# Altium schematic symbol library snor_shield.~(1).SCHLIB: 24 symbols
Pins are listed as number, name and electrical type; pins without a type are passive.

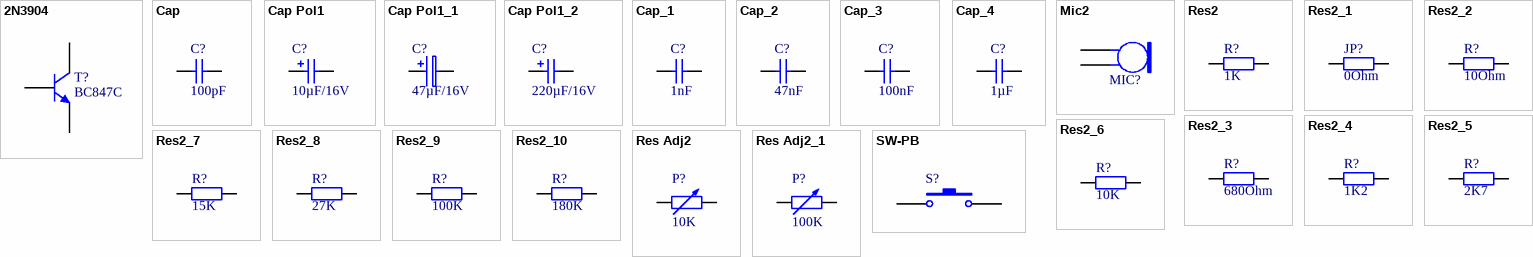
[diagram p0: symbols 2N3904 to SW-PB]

## 2N3904
designator T?, comment BC847C
NPN General Purpose Amplifier
footprint TO-92A (TO, Flat Index; 3 In-Line, Axial Leads; Body Dia. 4.5mm; Leads 0.51 x 0.48 mm (max))
simulation model 2N3904 (NPN)
signal-integrity model 2N3904
pins: 1 E, 2 B, 3 C

## Cap
designator C?  value 100pF  (hidden comment: Cap)
Capacitor
footprint RAD-0.3 (Radial Cap, Thru-Hole; 2 Leads; 0.3 in Pin Spacing)
simulation model CAP (Capacitor)
signal-integrity model Cap
pins: 1, 2

## Cap Pol1
designator C?  value 10µF/16V  (hidden comment: Cap Pol1)
Polarized Capacitor (Radial)
footprint RB7.6-15 (Polarized Capacitor (Radial); 2 Leads)
simulation model CAP (Capacitor)
signal-integrity model Cap Pol
pins: 1, 2
1 alternate drawing of the same symbol

## Cap Pol1_1
designator C?, comment value 47µF/16V  (hidden comment: Cap Pol1)
Polarized Capacitor (Radial)
footprint RB7.6-15 (Polarized Capacitor (Radial); 2 Leads)
simulation model CAP (Capacitor)
signal-integrity model Cap Pol
pins: 1, 2
1 alternate drawing of the same symbol

## Cap Pol1_2
designator C?, comment value 220µF/16V  (hidden comment: Cap Pol1)
Polarized Capacitor (Radial)
footprint RB7.6-15 (Polarized Capacitor (Radial); 2 Leads)
simulation model CAP (Capacitor)
signal-integrity model Cap Pol
pins: 1, 2
1 alternate drawing of the same symbol

## Cap_1
designator C?, comment value 1nF  (hidden comment: Cap)
Capacitor
footprint RAD-0.3 (Radial Cap, Thru-Hole; 2 Leads; 0.3 in Pin Spacing)
simulation model CAP (Capacitor)
signal-integrity model Cap
pins: 1, 2

## Cap_2
designator C?, comment value 47nF  (hidden comment: Cap)
Capacitor
footprint RAD-0.3 (Radial Cap, Thru-Hole; 2 Leads; 0.3 in Pin Spacing)
simulation model CAP (Capacitor)
signal-integrity model Cap
pins: 1, 2

## Cap_3
designator C?, comment value 100nF  (hidden comment: Cap)
Capacitor
footprint RAD-0.3 (Radial Cap, Thru-Hole; 2 Leads; 0.3 in Pin Spacing)
simulation model CAP (Capacitor)
signal-integrity model Cap
pins: 1, 2

## Cap_4
designator C?, comment value 1µF  (hidden comment: Cap)
Capacitor
footprint RAD-0.3 (Radial Cap, Thru-Hole; 2 Leads; 0.3 in Pin Spacing)
simulation model CAP (Capacitor)
signal-integrity model Cap
pins: 1, 2

## Mic2
designator MIC?  (value not drawn)
Microphone
footprint PIN2 (Microphone; 2 Leads)
pins: 1, 2

## Res2
designator R?  value 1K  (hidden comment: Res2)
Resistor
footprint AXIAL-0.4 (Axial Device, Thru-Hole; 2 Leads; 0.4 in Pin Spacing)
simulation model RESISTOR (Resistor)
signal-integrity model Res
pins: 1, 2

## Res2_1
designator JP?, comment value 0Ohm  (hidden comment: Res2)
Resistor
footprint AXIAL-0.4 (Axial Device, Thru-Hole; 2 Leads; 0.4 in Pin Spacing)
simulation model RESISTOR (Resistor)
signal-integrity model Res
pins: 1, 2

## Res2_2
designator R?, comment value 10Ohm  (hidden comment: Res2)
Resistor
footprint AXIAL-0.4 (Axial Device, Thru-Hole; 2 Leads; 0.4 in Pin Spacing)
simulation model RESISTOR (Resistor)
signal-integrity model Res
pins: 1, 2

## Res2_3
designator R?, comment value 680Ohm  (hidden comment: Res2)
Resistor
footprint AXIAL-0.4 (Axial Device, Thru-Hole; 2 Leads; 0.4 in Pin Spacing)
simulation model RESISTOR (Resistor)
signal-integrity model Res
pins: 1, 2

## Res2_4
designator R?, comment value 1K2  (hidden comment: Res2)
Resistor
footprint AXIAL-0.4 (Axial Device, Thru-Hole; 2 Leads; 0.4 in Pin Spacing)
simulation model RESISTOR (Resistor)
signal-integrity model Res
pins: 1, 2

## Res2_5
designator R?, comment value 2K7  (hidden comment: Res2)
Resistor
footprint AXIAL-0.4 (Axial Device, Thru-Hole; 2 Leads; 0.4 in Pin Spacing)
simulation model RESISTOR (Resistor)
signal-integrity model Res
pins: 1, 2

## Res2_6
designator R?, comment value 10K  (hidden comment: Res2)
Resistor
footprint AXIAL-0.4 (Axial Device, Thru-Hole; 2 Leads; 0.4 in Pin Spacing)
simulation model RESISTOR (Resistor)
signal-integrity model Res
pins: 1, 2

## Res2_7
designator R?, comment value 15K  (hidden comment: Res2)
Resistor
footprint AXIAL-0.4 (Axial Device, Thru-Hole; 2 Leads; 0.4 in Pin Spacing)
simulation model RESISTOR (Resistor)
signal-integrity model Res
pins: 1, 2

## Res2_8
designator R?, comment value 27K  (hidden comment: Res2)
Resistor
footprint AXIAL-0.4 (Axial Device, Thru-Hole; 2 Leads; 0.4 in Pin Spacing)
simulation model RESISTOR (Resistor)
signal-integrity model Res
pins: 1, 2

## Res2_9
designator R?, comment value 100K  (hidden comment: Res2)
Resistor
footprint AXIAL-0.4 (Axial Device, Thru-Hole; 2 Leads; 0.4 in Pin Spacing)
simulation model RESISTOR (Resistor)
signal-integrity model Res
pins: 1, 2

## Res2_10
designator R?, comment value 180K  (hidden comment: Res2)
Resistor
footprint AXIAL-0.4 (Axial Device, Thru-Hole; 2 Leads; 0.4 in Pin Spacing)
simulation model RESISTOR (Resistor)
signal-integrity model Res
pins: 1, 2

## Res Adj2
designator P?  value 10K  (hidden comment: Res Adj2)
Variable Resistor; Set Position: 0.5
footprint AXIAL-0.6 (Axial Device, Thru-Hole; 2 Leads; 0.6 in Pin Spacing)
simulation model VRES (Variable Resistor)
signal-integrity model Res Adj
pins: 1, 2

## Res Adj2_1
designator P?, comment value 100K  (hidden comment: Res Adj2)
Variable Resistor; Set Position: 0.5
footprint AXIAL-0.6 (Axial Device, Thru-Hole; 2 Leads; 0.6 in Pin Spacing)
simulation model VRES (Variable Resistor)
signal-integrity model Res Adj
pins: 1, 2

## SW-PB
designator S?  (value not drawn)
Switch
footprint SPST-2 (Switch; 2 Leads)
pins: 1, 2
